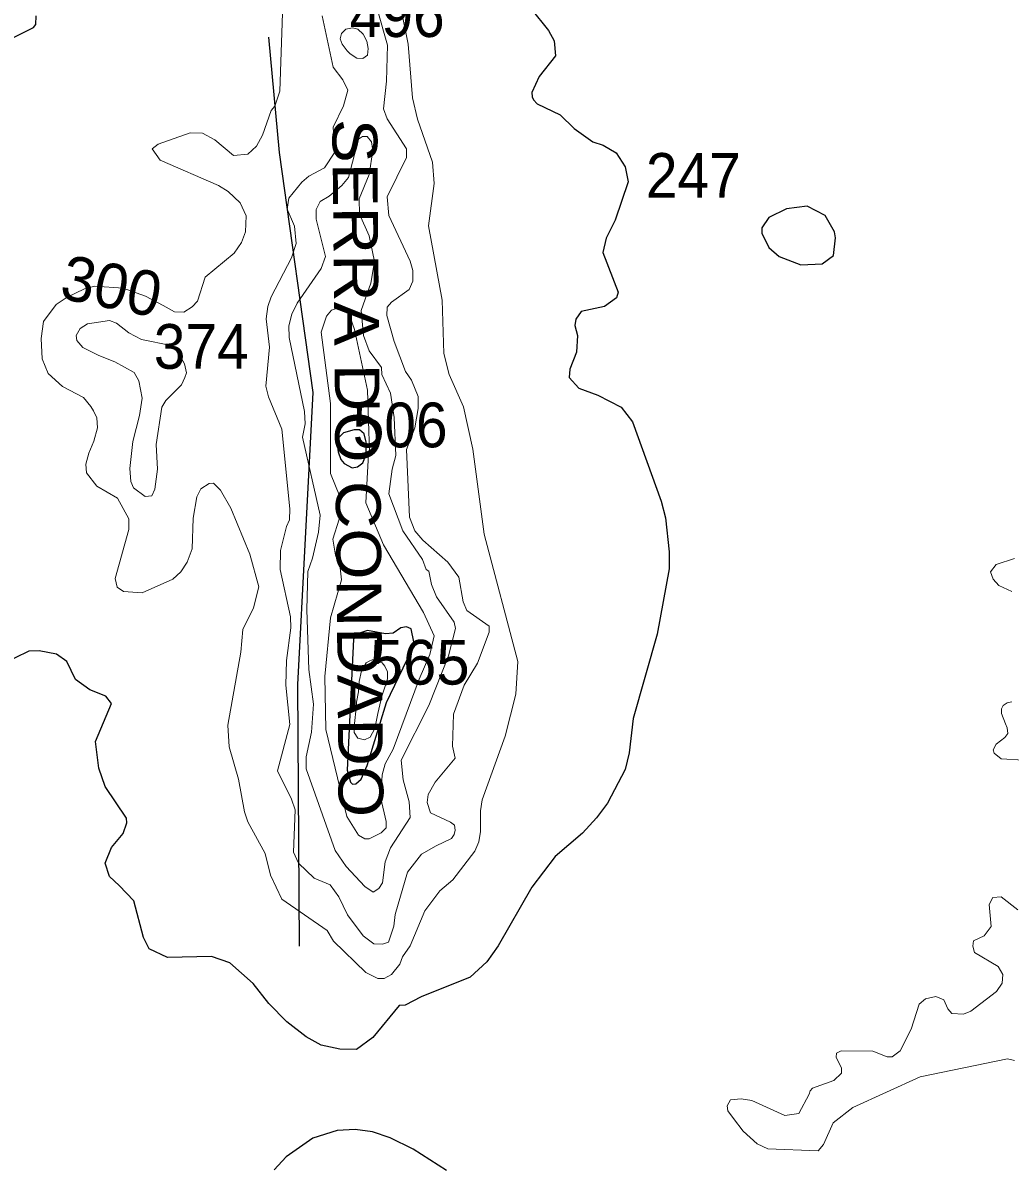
# Model space of a CAD drawing. Extents: x 499.9 to 555.3, y 9281.5 to 9336.8.
# Drawn here: x 510.675 to 514.206, y 9313.939 to 9318.021 of the extents above; entities that cross this region are included whole.
import ezdxf
from ezdxf.enums import TextEntityAlignment as Align

# ---------------------------------------------------------------- set-up
doc = ezdxf.new("R2010")
doc.units = 0
doc.header["$LTSCALE"] = 0.064
for name, color, linetype, lineweight in [('1', 7, 'Continuous', 25), ('2', 7, 'Continuous', 13), ('26', 7, 'Continuous', 25)]:
    doc.layers.add(name, color=color, linetype=linetype, lineweight=lineweight)
doc.layers.add('21', color=7, linetype='Continuous')
doc.layers.add('61', color=7, linetype='Continuous')

msp = doc.modelspace()

# ---------------------------------------------------------------- linework, layer by layer
at = {"layer": '1'}
for points in [[(512.429, 9318.1522), (512.5546, 9317.9936), (512.5754, 9317.957), (512.5803, 9317.9039), (512.5219, 9317.829), (512.4953, 9317.7725), (512.4964, 9317.7568), (512.5012, 9317.7455), (512.5146, 9317.732), (512.5964, 9317.6919), (512.6465, 9317.644), (512.7137, 9317.5955), (512.7509, 9317.5838), (512.7969, 9317.5562), (512.8289, 9317.5067), (512.8396, 9317.4525), (512.794, 9317.3155), (512.7617, 9317.2515), (512.7494, 9317.2004), (512.8043, 9317.0579), (512.7979, 9317.0377), (512.7555, 9317.0072), (512.6721, 9316.9888), (512.6532, 9316.9614), (512.6498, 9316.9387), (512.6585, 9316.9035), (512.6554, 9316.8432), (512.6319, 9316.7826), (512.6286, 9316.7523), (512.6635, 9316.715), (512.7318, 9316.6895), (512.8144, 9316.6464), (512.8559, 9316.5938), (512.9578, 9316.3107), (512.9735, 9316.251), (512.9864, 9316.1292), (512.9864, 9316.0688), (512.944, 9315.8352), (512.858, 9315.5328), (512.8433, 9315.4108), (512.8294, 9315.3514), (512.7656, 9315.2299), (512.727, 9315.1776), (512.6762, 9315.1236), (512.5785, 9315.04), (512.4958, 9314.9301), (512.3756, 9314.7205), (512.3349, 9314.6629), (512.2751, 9314.6076), (512.0991, 9314.5379), (512.0419, 9314.508), (512.0205, 9314.507), (511.927, 9314.3921)], [(510.5538, 9317.9246), (510.7135, 9318.0043), (510.7214, 9318.0154), (510.723, 9318.0464)], [(511.6193, 9314.4486), (511.5551, 9314.5145), (511.4983, 9314.5854), (511.4147, 9314.6588), (511.3495, 9314.6824), (511.1927, 9314.6779), (511.1267, 9314.7097), (511.1063, 9314.7499), (511.0716, 9314.8814), (511.0193, 9314.9356), (510.9846, 9314.9676), (510.9689, 9315.0153), (510.9923, 9315.0724), (511.0339, 9315.1222), (511.0464, 9315.1603), (511.0456, 9315.1765), (510.9697, 9315.2897), (510.9462, 9315.3558), (510.9346, 9315.4512), (510.9916, 9315.5871), (510.9719, 9315.6129), (510.9143, 9315.6359), (510.8631, 9315.6732), (510.8317, 9315.737), (510.7956, 9315.7633), (510.7328, 9315.7758), (510.6969, 9315.7743), (510.5991, 9315.7269)], [(511.927, 9314.3921), (511.8681, 9314.349), (511.8087, 9314.35), (511.7419, 9314.3644), (511.6878, 9314.3945), (511.6193, 9314.4486)], [(512.1907, 9313.9169), (512.0715, 9313.9924), (511.9893, 9314.0334), (511.9257, 9314.0555), (511.8637, 9314.0633), (511.7991, 9314.0601), (511.7117, 9314.0328), (511.6168, 9313.9652), (511.5737, 9313.9192)]]:
    msp.add_lwpolyline(points, dxfattribs=at)
for points in [[(513.5444, 9317.3326), (513.4798, 9317.3655), (513.4059, 9317.3559), (513.3427, 9317.3254), (513.3181, 9317.2886), (513.3178, 9317.2688), (513.3431, 9317.218), (513.3803, 9317.1858), (513.4577, 9317.1562), (513.5341, 9317.1589), (513.575, 9317.1896), (513.5816, 9317.2521), (513.578, 9317.2743)], [(511.8118, 9316.4601), (511.8238, 9316.4458), (511.8524, 9316.4298), (511.8716, 9316.433), (511.8907, 9316.4474), (511.9027, 9316.4769), (511.9035, 9316.5215), (511.8963, 9316.551), (511.8795, 9316.5653), (511.8596, 9316.5653), (511.8222, 9316.555), (511.8054, 9316.5382), (511.8014, 9316.5215), (511.8006, 9316.5047), (511.803, 9316.4872)], [(511.9066, 9315.3653), (511.9752, 9315.5901), (512.0497, 9315.7439), (512.0739, 9315.8071), (512.0639, 9315.8544), (512.0467, 9315.8609), (512.0272, 9315.8576), (511.9991, 9315.8388), (511.9719, 9315.836), (511.9074, 9315.8482), (511.8751, 9315.8377), (511.8573, 9315.8165), (511.8347, 9315.3485), (511.8463, 9315.3059), (511.854, 9315.2986), (511.8654, 9315.2997), (511.8855, 9315.3159)]]:
    msp.add_lwpolyline(points, close=True, dxfattribs=at)
at = {"layer": '2'}
for points in [[(511.6049, 9318.09), (511.5937, 9317.7772), (511.576, 9317.7239), (511.5635, 9317.7074), (511.532, 9317.6196), (511.5111, 9317.5808), (511.4793, 9317.5518), (511.428, 9317.5463), (511.362, 9317.6025), (511.3181, 9317.627), (511.2739, 9317.6284), (511.1592, 9317.5871), (511.1379, 9317.5712), (511.1657, 9317.5306), (511.3751, 9317.4395), (511.4092, 9317.4184), (511.4524, 9317.3778), (511.4743, 9317.3315), (511.4714, 9317.2738), (511.4568, 9317.2355), (511.4305, 9317.1977), (511.3272, 9317.1116), (511.2994, 9317.0261), (511.2804, 9317.0058), (511.2509, 9316.9861), (511.2169, 9316.988), (511.1764, 9317.0106), (511.1141, 9317.0436), (511.034, 9317.0719), (510.9322, 9317.0795), (510.8954, 9317.0701), (510.8331, 9317.0399), (510.7937, 9317.014), (510.7491, 9316.9535), (510.741, 9316.8924), (510.7443, 9316.8198), (510.7651, 9316.7672), (510.8167, 9316.7205), (510.8924, 9316.6808), (510.9176, 9316.6496), (510.9276, 9316.6339), (510.9392, 9316.6091), (510.9425, 9316.5727), (510.9293, 9316.5247), (510.9107, 9316.4819), (510.9001, 9316.4432), (510.9021, 9316.4119), (510.9393, 9316.3638), (511.0138, 9316.3207), (511.0539, 9316.2477), (511.0543, 9316.2096), (511.0053, 9316.0345), (511.0119, 9316.0034), (511.0349, 9315.987), (511.102, 9315.983), (511.2118, 9316.0314), (511.2404, 9316.0577), (511.2624, 9316.092), (511.2802, 9316.1406), (511.2839, 9316.2501), (511.2969, 9316.3258), (511.3118, 9316.3546), (511.3409, 9316.374), (511.3572, 9316.3752), (511.3821, 9316.3504), (511.4191, 9316.2861), (511.487, 9316.1205), (511.519, 9316.0045), (511.5001, 9315.9295), (511.4617, 9315.8516), (511.4545, 9315.7707), (511.4077, 9315.5093), (511.4125, 9315.4314), (511.4459, 9315.3168), (511.4675, 9315.1999), (511.4801, 9315.1632), (511.5413, 9315.0502), (511.5608, 9314.9731), (511.6016, 9314.887), (511.763, 9314.7754), (511.7862, 9314.7367), (511.9012, 9314.6248), (511.9448, 9314.6034), (511.9677, 9314.6029), (511.9933, 9314.6175), (512.0235, 9314.6541)], [(511.7451, 9318.0463), (511.7848, 9317.8632), (511.8199, 9317.8174), (511.8373, 9317.7808), (511.8218, 9317.7241), (511.7852, 9317.6483), (511.791, 9317.5585), (511.7542, 9317.503), (511.698, 9317.4729), (511.6729, 9317.4513), (511.6269, 9317.3945), (511.6209, 9317.3545), (511.6463, 9317.2943), (511.6525, 9317.2323), (511.636, 9317.1814), (511.563, 9317.0412), (511.5508, 9317.0071), (511.5453, 9316.9631), (511.5572, 9316.8614), (511.5446, 9316.7221), (511.5541, 9316.6832), (511.6016, 9316.5685), (511.6303, 9316.2826), (511.6286, 9316.2441), (511.6174, 9316.2201), (511.5967, 9316.1342), (511.5954, 9316.0664), (511.632, 9315.8969), (511.6335, 9315.858), (511.6178, 9315.7409), (511.6161, 9315.6524), (511.6304, 9315.5118), (511.586, 9315.3462), (511.6364, 9315.245), (511.6492, 9315.2068), (511.6432, 9315.0551), (511.6605, 9315.016), (511.7166, 9314.9627), (511.7739, 9314.938), (511.8056, 9314.895), (511.8358, 9314.8306), (511.8926, 9314.7562), (511.93, 9314.7278), (511.9615, 9314.7257)], [(512.2119, 9315.4338), (512.2153, 9315.5486), (512.2534, 9315.653), (512.3007, 9315.731), (512.3431, 9315.8421), (512.3434, 9315.8635), (512.2632, 9315.919), (512.2497, 9315.9505), (512.2347, 9316.0389), (512.1954, 9316.0926), (512.1052, 9316.1716), (512.0765, 9316.2046), (512.0584, 9316.2536), (512.0473, 9316.4951), (512.0773, 9316.5726), (512.0888, 9316.6425), (512.0888, 9316.6849), (512.065, 9316.7433), (512.044, 9316.7746), (512.0034, 9316.882), (511.9772, 9316.9741), (511.9778, 9317.0042), (511.9939, 9317.0224), (512.0569, 9317.0674), (512.0696, 9317.0972), (512.0696, 9317.1351), (512.0603, 9317.1694), (511.9839, 9317.3326), (511.9785, 9317.399), (512.0471, 9317.5398), (512.0473, 9317.5705), (511.9784, 9317.6778), (511.965, 9317.7137), (511.9758, 9317.8131), (511.9787, 9317.9411), (511.9423, 9318.071)], [(512.2128, 9314.9564), (512.2915, 9315.0584), (512.3053, 9315.0923), (512.3115, 9315.129), (512.3117, 9315.203), (512.3183, 9315.242), (512.4005, 9315.4696), (512.4382, 9315.62), (512.4453, 9315.737), (512.3244, 9316.193), (512.2843, 9316.497), (512.2512, 9316.6474), (512.2, 9316.7635), (512.1813, 9316.8384), (512.1747, 9317.0294), (512.1255, 9317.2951), (512.1459, 9317.4464), (512.1398, 9317.5228), (512.0871, 9317.677), (512.0682, 9317.7527), (512.0536, 9317.9453), (512.0301, 9318.0575)], [(514.212, 9315.9877), (514.1653, 9316.0093), (514.1456, 9316.031), (514.1362, 9316.0577), (514.1561, 9316.0837), (514.2223, 9316.1054)], [(514.2541, 9315.3842), (514.1739, 9315.3894), (514.149, 9315.4094), (514.1455, 9315.4211), (514.1558, 9315.4417), (514.1876, 9315.4651), (514.1975, 9315.48), (514.1961, 9315.4998), (514.1896, 9315.5141), (514.1756, 9315.5515), (514.1749, 9315.5678), (514.1816, 9315.5794), (514.1954, 9315.5897), (514.2127, 9315.5927)], [(512.1004, 9315.0482), (512.1532, 9315.0776), (512.2079, 9315.1044), (512.2176, 9315.1186), (512.2212, 9315.1338), (512.2186, 9315.152), (512.2042, 9315.1624), (512.1335, 9315.1954), (512.1206, 9315.2331), (512.1243, 9315.2611), (512.1498, 9315.3056), (512.2216, 9315.3912), (512.2119, 9315.4338)], [(511.9615, 9314.7257), (511.9833, 9314.7337), (512.0022, 9314.7905), (512.0066, 9314.8322), (512.0511, 9314.9838), (512.1004, 9315.0482)], [(512.0235, 9314.6541), (512.0325, 9314.6807), (512.0599, 9314.7207), (512.1122, 9314.8448), (512.1668, 9314.9164), (512.2128, 9314.9564)], [(513.7846, 9314.3232), (513.8133, 9314.3447), (513.8519, 9314.4224), (513.8809, 9314.5115), (513.9035, 9314.5311), (513.9407, 9314.5389), (513.9686, 9314.5275), (513.9829, 9314.4949), (513.9976, 9314.4784), (514.0392, 9314.4758), (514.0655, 9314.4868), (514.1577, 9314.5568), (514.178, 9314.5864), (514.1801, 9314.6181), (514.1634, 9314.6461), (514.0793, 9314.6959), (514.0731, 9314.7185), (514.0757, 9314.7385), (514.1132, 9314.756), (514.1384, 9314.7891), (514.131, 9314.8679), (514.1444, 9314.8925), (514.1747, 9314.8951), (514.2335, 9314.8485)], [(513.1963, 9314.1302), (513.1937, 9314.1478), (513.2065, 9314.1696), (513.2443, 9314.1731), (513.2829, 9314.1664), (513.4001, 9314.113), (513.45, 9314.1205), (513.4874, 9314.1902), (513.4912, 9314.2015), (513.499, 9314.211), (513.5752, 9314.2386), (513.6032, 9314.265), (513.6025, 9314.2825), (513.584, 9314.3216), (513.5854, 9314.3367), (513.6015, 9314.3451), (513.7155, 9314.3434), (513.7666, 9314.3236), (513.7846, 9314.3232)], [(514.2215, 9314.3103), (514.1968, 9314.3162), (513.8849, 9314.2513), (513.6438, 9314.1418), (513.5735, 9314.0877), (513.5386, 9314.0091), (513.5196, 9313.987)], [(513.5196, 9313.987), (513.3399, 9313.9936), (513.3013, 9314.0121), (513.251, 9314.057), (513.2163, 9314.1032), (513.1963, 9314.1302)]]:
    msp.add_lwpolyline(points, dxfattribs=at)
for points in [[(511.8453, 9317.9109), (511.8691, 9317.8955), (511.8913, 9317.894), (511.9074, 9317.9055), (511.9104, 9317.9293), (511.9051, 9317.9553), (511.892, 9317.9814), (511.8737, 9317.9982), (511.8537, 9318.0036), (511.83, 9317.9982), (511.8146, 9317.9837), (511.81, 9317.9637), (511.8169, 9317.9446), (511.8346, 9317.9208)], [(511.7387, 9316.2601), (511.6755, 9316.5389), (511.6844, 9316.5876), (511.6829, 9316.6314), (511.6275, 9316.8957), (511.6258, 9316.9378), (511.6372, 9316.9798), (511.6567, 9317.0189), (511.7424, 9317.1432), (511.7574, 9317.1853), (511.7245, 9317.3197), (511.7235, 9317.3543), (511.7388, 9317.3829), (511.7703, 9317.4011), (511.7922, 9317.4198), (511.8155, 9317.4399), (511.8392, 9317.4678), (511.8751, 9317.6049), (511.8893, 9317.6146), (511.9064, 9317.6151), (511.9216, 9317.596), (511.9262, 9317.5648), (511.9136, 9317.479), (511.8777, 9317.3916), (511.8788, 9317.337), (511.9136, 9317.2593), (511.9327, 9317.1683), (511.92, 9317.0897), (511.8852, 9316.9923), (511.8937, 9316.9036), (511.9136, 9316.8488), (511.9582, 9316.789), (511.9588, 9316.7637), (511.9904, 9316.6972), (512.0028, 9316.6099), (512.0091, 9316.4736), (511.9959, 9316.4254), (511.984, 9316.337), (512.0345, 9316.2047), (512.1049, 9316.1016), (512.1177, 9316.066), (512.127, 9316.0598), (512.1364, 9316.0123), (512.1549, 9315.9686), (512.2175, 9315.8778), (512.2222, 9315.8554), (512.197, 9315.7569), (512.1268, 9315.5799), (512.0286, 9315.3843), (512.0358, 9315.3143), (512.0569, 9315.2348), (512.0599, 9315.1792), (511.9899, 9315.0701), (511.971, 9315.0208), (511.9613, 9314.9452), (511.9486, 9314.9251), (511.9282, 9314.9121), (511.8984, 9314.932), (511.8315, 9315.0038), (511.7921, 9315.0614), (511.6879, 9315.3534), (511.688, 9315.3957), (511.7069, 9315.484), (511.7147, 9315.5842), (511.6973, 9315.708), (511.691, 9315.9216), (511.6939, 9316.0589), (511.7113, 9316.1063), (511.7323, 9316.1994)], [(511.8343, 9315.1829), (511.7581, 9315.4942), (511.7548, 9315.6837), (511.7753, 9315.8937), (511.8148, 9316.0292), (511.8102, 9316.0719), (511.7928, 9316.1173), (511.7835, 9316.1748), (511.8068, 9316.2463), (511.8086, 9316.3275), (511.7755, 9316.4094), (511.7751, 9316.6601), (511.742, 9316.9149), (511.7611, 9316.9728), (511.7786, 9316.9932), (511.8144, 9317.0057), (511.8387, 9316.9885), (511.8612, 9316.9248), (511.9073, 9316.7073), (511.9149, 9316.4878), (511.9117, 9316.4782), (511.9015, 9316.3044), (511.9646, 9316.1549), (512.1083, 9315.9121), (512.1459, 9315.8292), (512.1308, 9315.7617), (512.0925, 9315.6745), (511.9991, 9315.4235), (511.9709, 9315.371), (511.9604, 9315.3321), (511.9552, 9315.2475), (511.9741, 9315.1649), (511.9739, 9315.1426), (511.9566, 9315.1248), (511.9138, 9315.103), (511.8978, 9315.103), (511.8752, 9315.1163)], [(511.1012, 9316.6786), (511.0898, 9316.7415), (511.0733, 9316.7713), (511.0037, 9316.8093), (510.9466, 9316.8314), (510.8896, 9316.8604), (510.8678, 9316.8847), (510.8651, 9316.9036), (510.8796, 9316.9285), (510.9059, 9316.9447), (510.9849, 9316.9565), (511.0097, 9316.9471), (511.0544, 9316.9124), (511.0989, 9316.8886), (511.2054, 9316.8675), (511.2294, 9316.8444), (511.2528, 9316.8016), (511.2609, 9316.7699), (511.2547, 9316.7531), (511.2421, 9316.7266), (511.1858, 9316.6703), (511.172, 9316.6472), (511.1513, 9316.5137), (511.156, 9316.4253), (511.1467, 9316.3536), (511.1367, 9316.3302), (511.1127, 9316.3269), (511.0704, 9316.3586), (511.0608, 9316.3808), (511.0575, 9316.4278), (511.0687, 9316.524), (511.0924, 9316.6164)], [(511.9032, 9315.7327), (511.8857, 9315.7039), (511.8775, 9315.6659), (511.8754, 9315.6288), (511.8682, 9315.5918), (511.8682, 9315.5805), (511.86, 9315.5044), (511.86, 9315.4828), (511.8734, 9315.4633), (511.897, 9315.4571), (511.9176, 9315.4663), (511.9341, 9315.4972), (511.9444, 9315.5517), (511.9588, 9315.6134), (511.9711, 9315.6484), (511.9793, 9315.6751), (511.9793, 9315.6998), (511.9701, 9315.7204), (511.9598, 9315.7327), (511.9341, 9315.743), (511.9238, 9315.743), (511.9135, 9315.7389)]]:
    msp.add_lwpolyline(points, close=True, dxfattribs=at)
at = {"layer": '26'}
msp.add_lwpolyline([(511.553, 9317.97), (511.5915, 9317.5575), (511.7125, 9316.6995), (511.6575, 9315.6545), (511.663, 9314.7195)], dxfattribs=at)

# ---------------------------------------------------------------- texts
at = {"layer": '21', "width": 0.95}
for s, p in [('496', (511.8443, 9317.9708)), ('247', (512.9035, 9317.3956)), ('374', (511.1434, 9316.784)), ('506', (511.8549, 9316.5031))]:
    msp.add_text(s, height=0.16, dxfattribs=at).set_placement(p)
at = {"layer": '21'}
msp.add_text('565', height=0.16, dxfattribs=at).set_placement((511.916, 9315.6545))
at = {"layer": '26', "width": 1.1}
msp.add_text('SERRA DO CONDADO', height=0.16, rotation=270.531, dxfattribs=at).set_placement((511.7934, 9316.4284), align=Align.CENTER)
at = {"layer": '61'}
msp.add_text('300', height=0.16, rotation=348.69, dxfattribs=at).set_placement((510.9769, 9317.0017), align=Align.CENTER)

doc.saveas('drawing.dxf')
